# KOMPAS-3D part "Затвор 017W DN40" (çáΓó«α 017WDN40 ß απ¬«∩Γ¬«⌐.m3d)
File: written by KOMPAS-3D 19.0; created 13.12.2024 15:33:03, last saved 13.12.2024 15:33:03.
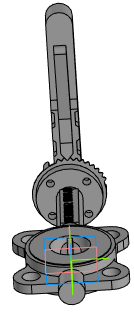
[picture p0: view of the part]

Document properties: Автор: Евгений; Полное имя файла: ..\Затвор 017WDN40.a3d

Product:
- Part/product: Затвор 017W DN40
    Масса: 3.54737

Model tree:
1. Операция без истории:1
